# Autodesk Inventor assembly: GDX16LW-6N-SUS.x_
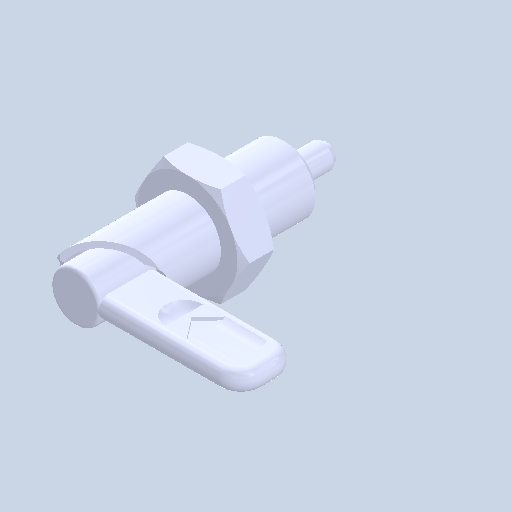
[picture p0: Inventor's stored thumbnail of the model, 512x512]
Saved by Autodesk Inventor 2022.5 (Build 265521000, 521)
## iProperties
Created: 2024-06
Part Number: GDX16LW-6N-SUS.x_
Document SubType Name: Assembly
Designer: ImaoCorp
Author: ImaoCorp
Sending System: SOLIDWORKS 2022-2022290
MC: AMD64
MC_MODEL: Intel64 Family 6 Model 60 Stepping 3, GenuineIntel
OS: Windows_NT
FRU: Parasolid Version 33.1, build 260,  4-25-2022
FORMAT: text
GUISE: transmit
KEY: FILEGDX16LW-6N-SUS.x_t
DATE: Wed Jun 12 09:32:35 2024
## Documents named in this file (4)
- Y:\5.更新分\2024年対応\xxxx_GDX\データ_imao品番\gdx16lw-6n-sus\GDX16LW-6N-SUS.x_.iam
- Y:\5.更新分\2024年対応\xxxx_GDX\データ_imao品番\gdx16lw-6n-sus\GDX16LW-6N-SUS_01.ipt
- Y:\5.更新分\2024年対応\xxxx_GDX\データ_imao品番\gdx16lw-6n-sus\GDX16LW-6N-SUS_02.ipt
- Y:\5.更新分\2024年対応\xxxx_GDX\データ_imao品番\gdx16lw-6n-sus\GDX16LW-6N-SUS_03.ipt
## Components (3 placed, 3 different names)
1. GDX16LW-6N-SUS_01
2. GDX16LW-6N-SUS_02
3. GDX16LW-6N-SUS_03
